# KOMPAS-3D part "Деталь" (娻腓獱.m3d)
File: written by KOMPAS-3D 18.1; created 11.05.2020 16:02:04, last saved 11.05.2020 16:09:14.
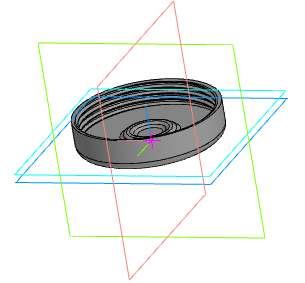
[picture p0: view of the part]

Document properties: Автор: yarkov_aleksei@mail.ru; Полное имя файла: C:\Users\Leha\Desktop\Крышка.m3d

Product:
- Part/product: Деталь
    Материал: Фторопласт-4  ГОСТ 10007-80 Е (density 2200 kg/m3)
    Масса: 0.0058645

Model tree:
1. Смещенная плоскость:1
     Расстояние = 2
2. Эскиз:3
3. Элемент выдавливания:2
     Расстояние 1 = 6
4. Эскиз:4
5. Спираль:1
     Число витков = 7; Шаг = 1.5; Высота = 10.5; Диаметр 1 = 33.13; Диаметр 2 = 10
6. Эскиз:5
7. Элемент по траектории:1
8. Эскиз:6
9. Элемент выдавливания:3
     Расстояние 1 = 2
10. Скругление:1  (with: Элемент выдавливания:3)
     Радиус = 2
11. Эскиз:7  (with: Элемент выдавливания:3)
12. Элемент выдавливания:4
     Расстояние 1 = 1
13. Скругление:2  (with: Элемент выдавливания:4)  (labels: Фторопласт-4  ГОСТ 10007-80 Е)
     Радиус = 1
